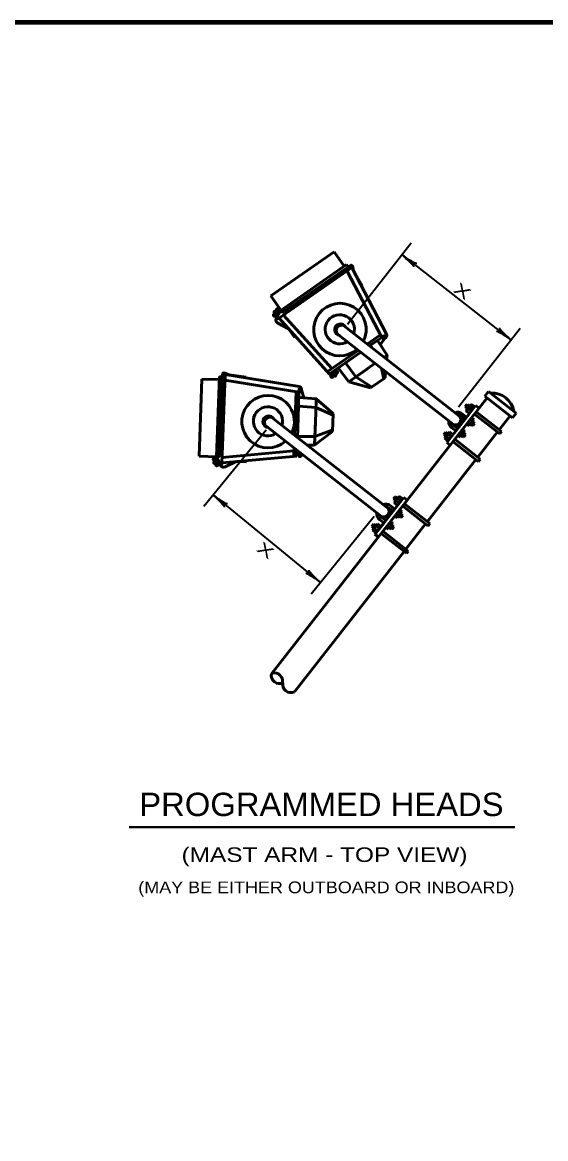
# Model space of a CAD drawing. Extents: x -370 to 486, y -203 to 341.
# Drawn here: x 151.7 to 259.2, y 105.4 to 334.9 of the extents above; entities that cross this region are included whole.
import ezdxf
from ezdxf.enums import TextEntityAlignment as Align

# ---------------------------------------------------------------- set-up
doc = ezdxf.new("R2010")
doc.units = 0
doc.header["$LTSCALE"] = 0.96
doc.layers.add('1', color=7, linetype='Continuous', lineweight=53)

msp = doc.modelspace()

# ---------------------------------------------------------------- linework, layer by layer
at = {"layer": '1', "lineweight": 35}
for p, q in [((231.5862, 289.4984), (218.52, 272.7744)), ((229.7308, 287.1237), (252.1531, 269.6055)), ((254.0085, 271.9802), (241.3529, 255.7817)), ((188.9645, 235.4094), (201.7675, 251.1128)), ((190.8689, 237.7452), (212.9223, 219.7649)), ((211.0181, 217.4291), (224.0076, 233.3611))]:
    msp.add_line(p, q, dxfattribs=at)
at = {"layer": '1'}
for p, q in [((202.7343, 278.6676), (215.7699, 287.738)), ((217.8262, 284.7831), (215.7699, 287.738)), ((204.7827, 275.7075), (218.3263, 285.1314)), ((205.3716, 275.3864), (219.1616, 284.9816)), ((218.3263, 285.1314), (218.6691, 284.6387)), ((219.5046, 284.8449), (219.7533, 283.8194)), ((204.3467, 274.0124), (219.4031, 284.4892)), ((218.4101, 283.7984), (225.5482, 270.1252)), ((219.4031, 284.4892), (226.5416, 270.8164)), ((219.7533, 283.8194), (221.5288, 280.735)), ((204.7905, 275.713), (202.7343, 278.6676)), ((204.4566, 275.1176), (203.6276, 275.5168)), ((203.9471, 275.3699), (203.864, 275.6951)), ((204.0999, 275.2898), (204.3107, 275.5505)), ((203.7857, 275.1028), (203.4609, 275.0169)), ((204.3083, 274.8566), (203.4973, 275.247)), ((203.966, 275.0137), (203.8414, 274.7022)), ((204.4439, 274.0801), (214.8223, 262.5918)), ((205.3749, 274.7279), (215.3087, 263.7314)), ((204.193, 273.105), (206.4094, 271.9368)), ((206.4094, 271.9368), (207.6553, 270.1554)), ((216.4089, 270.9083), (240.2859, 252.2554)), ((217.6995, 272.5607), (241.5796, 253.9099)), ((222.5512, 268.7714), (225.2682, 270.662)), ((223.0465, 268.3846), (225.5482, 270.1252)), ((226.6278, 266.4908), (224.6757, 269.5158)), ((226.2837, 270.0239), (225.2391, 268.6428)), ((214.3158, 263.0409), (220.7493, 267.5176)), ((214.7211, 262.5918), (221.2445, 267.1307)), ((223.4859, 268.0414), (223.1978, 268.4879)), ((220.2251, 262.0358), (218.0668, 264.9172)), ((218.7477, 261.0075), (224.2138, 264.811)), ((191.6126, 245.5798), (192.1851, 262.0695)), ((192.1851, 262.0695), (192.7848, 262.0486)), ((192.2224, 245.8587), (192.8056, 262.6485)), ((192.7083, 244.2148), (193.3445, 262.5466)), ((193.1205, 262.8411), (194.0906, 262.4255)), ((193.3445, 262.5466), (208.5679, 260.0672)), ((194.0906, 262.4255), (197.6237, 261.9984)), ((215.4989, 262.6542), (215.2177, 262.4719)), ((215.2795, 262.9594), (215.8188, 262.2394)), ((215.5196, 263.1388), (216.0593, 262.4191)), ((215.6219, 262.4937), (215.6002, 262.1589)), ((215.7447, 262.8383), (215.9596, 263.0956)), ((215.8524, 262.7042), (216.1873, 262.6852)), ((218.7477, 261.0075), (216.5894, 263.8892)), ((218.7477, 261.0075), (222.6089, 263.6946)), ((220.2251, 262.0358), (223.5125, 259.9375)), ((223.2662, 259.766), (226.2209, 261.8226)), ((225.51, 263.7984), (225.9748, 261.6507)), ((226.3369, 263.1525), (226.2209, 261.8226)), ((188.0152, 245.7139), (188.5664, 261.5851)), ((192.1642, 261.4604), (188.5664, 261.5851)), ((193.3023, 261.3378), (208.526, 258.8576)), ((218.7477, 261.0075), (223.2662, 259.766)), ((247.2057, 257.6996), (202.8781, 200.9628)), ((207.7376, 253.4534), (207.9285, 258.9553)), ((208.3438, 253.6179), (208.526, 258.8576)), ((212.0824, 257.5439), (208.491, 257.794)), ((209.0478, 259.3858), (209.5275, 257.7218)), ((247.4715, 259.0147), (246.7328, 258.069)), ((246.7328, 258.069), (252.4065, 253.6364)), ((247.4715, 259.0147), (253.1452, 254.5821)), ((212.0201, 255.7442), (208.4281, 255.9949)), ((212.0201, 255.7445), (215.5658, 254.1204)), ((214.5805, 255.3104), (215.5756, 254.4206)), ((243.0977, 256.3404), (242.7283, 255.8676)), ((242.7283, 255.8676), (243.9105, 254.9441)), ((243.9067, 256.4013), (242.8651, 255.0679)), ((242.8651, 255.0679), (243.5743, 254.5139)), ((243.1234, 256.1299), (242.9387, 255.8935)), ((243.3341, 256.1557), (242.9647, 255.6829)), ((243.0977, 256.3404), (244.2799, 255.4169)), ((243.3599, 255.9452), (243.1752, 255.7088)), ((243.9067, 256.4013), (244.6159, 255.8473)), ((244.834, 256.1261), (245.5434, 255.5719)), ((244.9893, 254.8627), (250.1901, 250.7996)), ((202.9243, 253.6478), (226.8041, 234.9973)), ((207.617, 249.9827), (207.7374, 253.4534)), ((208.2019, 249.5259), (208.344, 253.6179)), ((211.7495, 247.9494), (211.9805, 254.6047)), ((211.7495, 247.9494), (211.9124, 252.651)), ((215.4512, 250.8227), (215.5756, 254.4206)), ((239.9034, 252.5544), (240.0038, 252.3874)), ((241.8041, 253.9152), (242.6129, 253.2832)), ((242.087, 254.4556), (242.9823, 253.7561)), ((243.3222, 252.729), (244.2678, 251.9902)), ((244.46, 253.2108), (243.4994, 251.9813)), ((243.6916, 253.2018), (244.6372, 252.463)), ((243.9872, 253.5801), (244.46, 253.2108)), ((244.1715, 252.5984), (244.0237, 252.4092)), ((244.4007, 252.6478), (244.0313, 252.175)), ((244.6199, 254.3899), (249.8207, 250.3268)), ((251.9337, 254.0058), (249.7173, 251.169)), ((253.1452, 254.5821), (252.4065, 253.6364)), ((201.6335, 251.9957), (225.5104, 233.3429)), ((211.7495, 247.9494), (215.4512, 250.8227)), ((211.8116, 249.7485), (215.4616, 251.1227)), ((238.665, 250.6668), (238.2956, 250.194)), ((239.474, 250.7277), (238.4324, 249.3943)), ((238.6907, 250.4563), (238.506, 250.2199)), ((238.9014, 250.4821), (238.532, 250.0093)), ((238.665, 250.6668), (239.8473, 249.7432)), ((238.9272, 250.2716), (238.7425, 250.0352)), ((240.6784, 250.807), (238.9238, 248.5611)), ((239.474, 250.7277), (240.1833, 250.1736)), ((239.8782, 251.6171), (240.7682, 250.9219)), ((240.2476, 252.0899), (241.1375, 251.3947)), ((241.4775, 250.3678), (242.4232, 249.6293)), ((242.6152, 250.8496), (241.6548, 249.6203)), ((241.8469, 250.8406), (242.7924, 250.102)), ((242.1424, 251.2189), (242.6152, 250.8496)), ((242.5559, 250.2867), (242.1867, 249.814)), ((243.0267, 252.3507), (243.4994, 251.9813)), ((244.408, 252.4137), (244.2602, 252.2245)), ((244.6372, 252.463), (244.2678, 251.9902)), ((249.3479, 250.6962), (245.2846, 245.4953)), ((250.1901, 250.7996), (249.8207, 250.3268)), ((211.8116, 249.7485), (208.2116, 249.7475)), ((211.7495, 247.9494), (210.2208, 247.9491)), ((238.2956, 250.194), (239.4779, 249.2704)), ((238.4324, 249.3943), (239.1417, 248.8402)), ((238.9238, 248.5611), (239.633, 248.007)), ((240.1871, 248.7162), (245.388, 244.6531)), ((240.5566, 249.1891), (245.7574, 245.1259)), ((241.182, 249.9896), (241.6548, 249.6203)), ((242.3268, 250.2373), (242.1791, 250.0482)), ((242.5633, 250.0526), (242.4156, 249.8635)), ((242.7924, 250.102), (242.4232, 249.6293)), ((191.6128, 245.5892), (188.0152, 245.7139)), ((192.7122, 244.3334), (208.0707, 245.7512)), ((192.7516, 245.4668), (207.5079, 246.8289)), ((207.4683, 245.6956), (207.5272, 247.3915)), ((208.0707, 245.7512), (208.1118, 246.9348)), ((208.1085, 246.3429), (208.8693, 246.3431)), ((208.1088, 246.6427), (208.4853, 246.643)), ((208.4842, 246.3357), (208.4616, 246.0013)), ((208.6865, 246.338), (208.9415, 246.1199)), ((191.382, 244.7086), (191.0719, 244.8368)), ((191.8894, 244.9652), (191.073, 244.5408)), ((192.0094, 244.69), (191.2109, 244.2748)), ((191.4991, 244.4193), (191.3733, 244.1078)), ((191.5377, 244.7829), (191.4554, 245.1078)), ((191.6785, 244.5102), (191.8533, 244.2238)), ((193.3425, 243.5481), (195.606, 244.6222)), ((195.606, 244.6222), (197.7787, 244.5521)), ((244.9152, 245.0225), (234.9415, 232.2567)), ((245.7574, 245.1259), (245.388, 244.6531)), ((228.3222, 237.4279), (227.9528, 236.9551)), ((227.9528, 236.9551), (229.135, 236.0316)), ((229.1312, 237.4888), (228.0896, 236.1554)), ((228.3479, 237.2174), (228.1632, 236.981)), ((228.5586, 237.2432), (228.1892, 236.7704)), ((228.3222, 237.4279), (229.5044, 236.5044)), ((228.5844, 237.0327), (228.3997, 236.7963)), ((229.1312, 237.4888), (229.8404, 236.9348)), ((230.0585, 237.2136), (230.7675, 236.6597)), ((227.0286, 235.0027), (227.8374, 234.3707)), ((227.3115, 235.5431), (228.2068, 234.8436)), ((228.0896, 236.1554), (228.7988, 235.6014)), ((229.6845, 234.2983), (228.7239, 233.0688)), ((228.9161, 234.2893), (229.8617, 233.5505)), ((229.2117, 234.6676), (229.6845, 234.2983)), ((229.8444, 235.4774), (235.0452, 231.4143)), ((230.2138, 235.9502), (235.4146, 231.8871)), ((225.9029, 231.8945), (224.1483, 229.6486)), ((225.1027, 232.7046), (225.9927, 232.0094)), ((225.4721, 233.1774), (226.362, 232.4822)), ((227.8397, 231.9371), (226.8793, 230.7078)), ((227.0714, 231.9281), (228.0169, 231.1895)), ((227.3669, 232.3064), (227.8397, 231.9371)), ((228.2512, 233.4382), (228.7239, 233.0688)), ((228.5467, 233.8165), (229.4923, 233.0777)), ((229.396, 233.6859), (229.2482, 233.4967)), ((229.6252, 233.7353), (229.2558, 233.2625)), ((229.6325, 233.5012), (229.4847, 233.312)), ((229.8617, 233.5505), (229.4923, 233.0777)), ((235.4146, 231.8871), (235.0452, 231.4143)), ((223.8895, 231.7543), (223.5201, 231.2815)), ((223.5201, 231.2815), (224.7024, 230.3579)), ((224.6985, 231.8152), (223.6569, 230.4818)), ((223.6569, 230.4818), (224.3662, 229.9277)), ((223.9152, 231.5438), (223.7305, 231.3074)), ((224.1259, 231.5696), (223.7565, 231.0968)), ((223.8895, 231.7543), (225.0718, 230.8307)), ((224.1517, 231.3591), (223.967, 231.1227)), ((224.1483, 229.6486), (224.8572, 229.0948)), ((224.6985, 231.8152), (225.4078, 231.2611)), ((225.4116, 229.8037), (230.6125, 225.7406)), ((225.7811, 230.2766), (230.9819, 226.2134)), ((226.4065, 231.0771), (226.8793, 230.7078)), ((226.702, 231.4553), (227.6477, 230.7168)), ((227.5513, 231.3248), (227.4036, 231.1357)), ((227.7804, 231.3742), (227.4112, 230.9015)), ((227.7878, 231.1401), (227.6401, 230.951)), ((228.0169, 231.1895), (227.6477, 230.7168)), ((234.5721, 231.7839), (230.5088, 226.583)), ((230.1393, 226.1103), (207.6061, 197.2689)), ((230.9819, 226.2134), (230.6125, 225.7406))]:
    msp.add_line(p, q, dxfattribs=at)
at = {"layer": '1', "lineweight": 40}
msp.add_line((173.6425, 169.4544), (252.888, 169.4544), dxfattribs=at)
at = {"layer": '1', "lineweight": 158}
msp.add_lwpolyline([(479.406, 334.9398), (-312.294, 334.8398), (-312.194, -191.1602)], dxfattribs=at)
at = {"layer": '1'}
for points in [[(204.7827, 275.7075), (203.7907, 273.9127), (204.3467, 274.0124)], [(226.0162, 266.0652), (226.6278, 266.4908), (226.5541, 265.6451)], [(211.9806, 254.6047), (212.0824, 257.5439), (214.5804, 255.3103)], [(244.834, 256.1261), (243.0794, 253.8803), (240.6784, 250.807)], [(191.6126, 245.5798), (192.4548, 243.71), (192.7083, 244.2148)], [(230.0585, 237.2136), (228.3039, 234.9678), (225.9029, 231.8945)]]:
    msp.add_lwpolyline(points, dxfattribs=at)
for centre in [(219.1665, 284.6976), (226.0531, 270.3695), (193.0359, 262.4821), (208.633, 259.4083)]:
    msp.add_circle(centre, 0.1221, dxfattribs=at)
for centre, radius, start, end in [((219.2531, 284.7211), 0.2761, 302.89292, 109.35881), ((203.5522, 275.3868), 0.1505, 59.95241, 248.62496), ((204.135, 275.7706), 0.2816, 308.58522, 195.64631), ((205.2111, 275.7924), 0.4368, 191.23275, 291.55987), ((216.9615, 271.7501), 5.4, 333.68871, 311.29261), ((203.5525, 274.7402), 0.2915, 108.32387, 352.5212), ((204.5035, 273.7638), 0.7282, 168.18066, 244.76157), ((216.9241, 271.8038), 3, 342.98256, 302.06743), ((217.0786, 271.7134), 1.2063, 23.95779, 262.9292), ((217.2649, 271.5757), 1.0766, 66.19313, 220.65033), ((225.983, 270.5599), 0.6145, 224.97004, 24.69248), ((193.069, 262.5655), 0.2761, 356.07364, 162.53953), ((215.3111, 262.1954), 0.2915, 108.60971, 352.80704), ((215.9455, 262.3199), 0.1505, 212.50594, 41.17849), ((216.2097, 262.9659), 0.2816, 265.48459, 152.54568), ((208.4385, 259.4663), 0.6145, 278.15075, 77.87319), ((202.1956, 252.8288), 5.4, 334.34216, 311.30255), ((248.3694, 254.3163), 4.3497, 8.39612, 95.60566), ((202.1576, 252.8822), 3, 343.63601, 302.72088), ((202.3132, 252.7935), 1.2063, 24.61124, 263.58265), ((202.501, 252.6579), 1.0766, 66.84658, 221.30377), ((240.6726, 252.7204), 1.3596, 168.40396, 234.24561), ((240.9281, 253.0859), 1.2063, 202.49407, 81.46547), ((240.7458, 253.2288), 1.0766, 244.77294, 39.23013), ((241.2149, 253.4187), 1.3596, 49.4358, 115.27744), ((191.8013, 245.9736), 0.4368, 244.41346, 344.74058), ((208.7389, 245.9103), 0.2915, 161.79042, 45.98775), ((191.1738, 245.0991), 0.2816, 1.76594, 248.82702), ((191.1319, 244.4025), 0.1505, 113.13313, 301.80568), ((191.6497, 244.0153), 0.2915, 161.50458, 45.70191), ((193.0013, 244.1914), 0.7282, 221.36138, 297.94229), ((226.1526, 234.1734), 1.2063, 202.49407, 81.46547), ((225.9703, 234.3163), 1.0766, 244.77294, 39.23013), ((226.4394, 234.5062), 1.3596, 49.4358, 115.27744), ((225.8971, 233.8079), 1.3596, 168.40396, 234.24561), ((204.5077, 200.6122), 1.6669, 167.85849, 296.14028), ((203.4334, 199.447), 1.7359, 343.66244, 103.21923), ((206.8468, 198.7333), 1.6497, 166.59364, 297.40514)]:
    msp.add_arc(centre, radius, start, end, dxfattribs=at)
at = {"layer": '1', "lineweight": 35}
for centre, major_axis, ratio, start_param, end_param in [((230.634, 286.0958), (1.5312, -1.4638), 0.07063, 6.28230741, 8.55970261), ((230.634, 286.0958), (1.5312, -1.4638), 0.07063, 6.28230741, 8.55970261), ((230.9668, 286.5788), (-1.8039, 1.1716), 0.122415, 0.89635335, 3.14159265), ((230.9668, 286.5788), (-1.8039, 1.1716), 0.122415, 0.89635335, 3.14159265), ((250.9171, 270.1504), (1.8039, -1.1716), 0.122415, 0.89635335, 3.14159265), ((250.9171, 270.1504), (1.8039, -1.1716), 0.122415, 0.89635335, 3.14159265), ((251.2499, 270.6334), (-1.5312, 1.4638), 0.07063, 6.28230741, 8.55970261), ((251.2499, 270.6334), (-1.5312, 1.4638), 0.07063, 6.28230741, 8.55970261), ((191.7506, 236.6987), (1.5004, -1.4953), 0.07063, 6.28230741, 8.55970261), ((191.7506, 236.6987), (1.5004, -1.4953), 0.07063, 6.28230741, 8.55970261), ((192.0933, 237.1747), (-1.7792, 1.2088), 0.122415, 0.89635335, 3.14159265), ((192.0933, 237.1747), (-1.7792, 1.2088), 0.122415, 0.89635335, 3.14159265), ((211.6979, 220.3354), (1.7792, -1.2088), 0.122415, 0.89635335, 3.14159265), ((211.6979, 220.3354), (1.7792, -1.2088), 0.122415, 0.89635335, 3.14159265), ((212.0406, 220.8114), (-1.5004, 1.4953), 0.07063, 6.28230741, 8.55970261), ((212.0406, 220.8114), (-1.5004, 1.4953), 0.07063, 6.28230741, 8.55970261)]:
    msp.add_ellipse(centre, major_axis=major_axis, ratio=ratio, start_param=start_param, end_param=end_param, dxfattribs=at)

# ---------------------------------------------------------------- texts
at = {"layer": '1', "width": 1.55}
for p in [(241.4277, 278.6753), (200.9761, 225.375)]:
    msp.add_text('X', height=2.4, rotation=324.999, dxfattribs=at).set_placement(p, align=Align.CENTER)
at = {"layer": '1'}
for s, height, width, p in [('PROGRAMMED HEADS', 4.8, 1.05, (213.1492, 171.7072)), ('(MAST ARM - TOP VIEW)', 3, 1.25, (213.7786, 162.2665)), ('(MAY BE EITHER OUTBOARD OR INBOARD)', 2.4, 1.15, (214.1519, 155.8438))]:
    msp.add_text(s, height=height, dxfattribs=dict(at, width=width)).set_placement(p, align=Align.CENTER)

doc.saveas('drawing.dxf')
